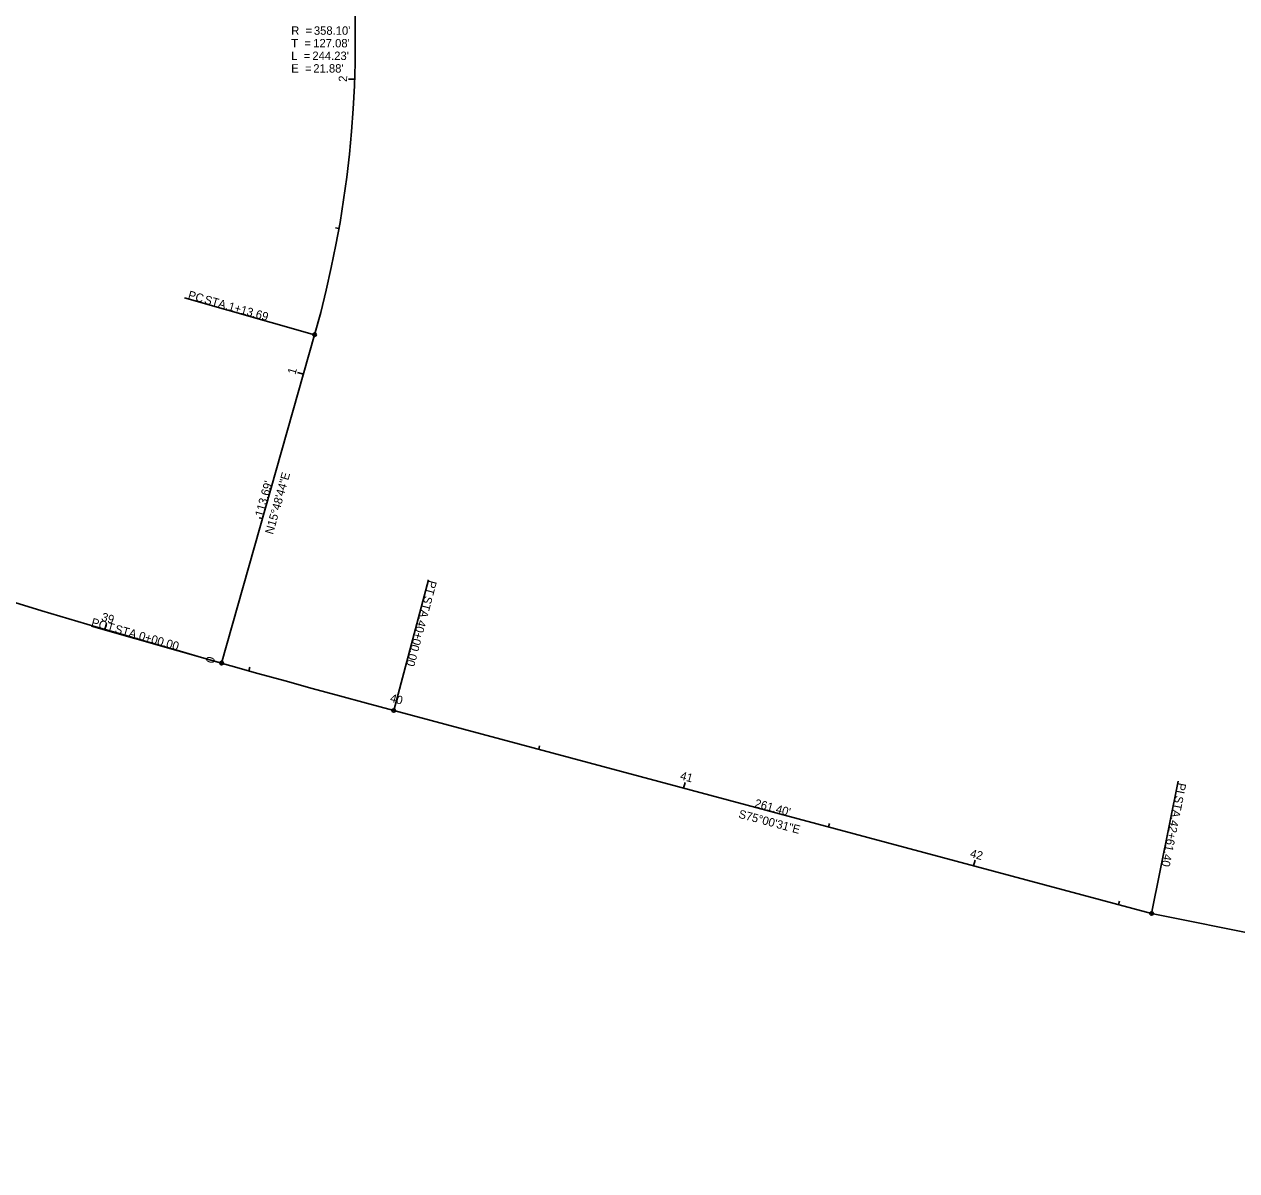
# Model space of a CAD drawing. Extents: x 1821160 to 1822741, y 497996 to 498758.
# Drawn here: x 1821926.9 to 1822330.8, y 497996.7 to 498378.6 of the extents above; entities that cross this region are included whole.
import ezdxf

# ---------------------------------------------------------------- set-up
doc = ezdxf.new("R2010")
doc.units = 0
for name, color, linetype in [('LT_X_Luminaires', 7, 'Continuous'), ('SC_Scratch1', 7, 'Continuous'), ('SC_Scratch20', 7, 'Continuous'), ('SV_P_Mon_Cells_Set', 7, 'Continuous'), ('SV_X_Control_Cells_Found', 7, 'Continuous'), ('SV_X_Mon_Cells_Found', 7, 'Continuous')]:
    doc.layers.add(name, color=color, linetype=linetype)

msp = doc.modelspace()

# ---------------------------------------------------------------- linework, layer by layer
at = {"layer": 'SC_Scratch1'}
for p, q in [((1822036.92, 498360.26), (1822034.92, 498360.33)), ((1822031.69, 498310.57), (1822030.51, 498310.78)), ((1822019.86, 498262.02), (1822017.93, 498262.57)), ((1822006.23, 498213.92), (1822005.08, 498214.24)), ((1821953.66, 498177.03), (1821954.22, 498178.95)), ((1821992.61, 498165.81), (1821990.68, 498166.35)), ((1822001.72, 498163.24), (1822002.04, 498164.4)), ((1822049.94, 498150.02), (1822050.46, 498151.95)), ((1822098.24, 498137.09), (1822098.55, 498138.25)), ((1822146.54, 498124.15), (1822147.05, 498126.08)), ((1822194.84, 498111.22), (1822195.15, 498112.38)), ((1822243.13, 498098.29), (1822243.65, 498100.22)), ((1822291.43, 498085.35), (1822291.74, 498086.51))]:
    msp.add_line(p, q, dxfattribs=at)
at = {"layer": 'SV_P_Mon_Cells_Set'}
for p, q in [((1821992.61, 498165.81), (1822023.59, 498275.19)), ((1822049.94, 498150.02), (1822302.44, 498082.4)), ((1822302.44, 498082.4), (1822729.2, 497996.72))]:
    msp.add_line(p, q, dxfattribs=at)
for centre, radius, start, end in [((1821679.04, 498372.77), 358.1, 344.1879, 23.264), ((1823136.37, 502207.06), 4199.99, 246.82358, 255.00869)]:
    msp.add_arc(centre, radius, start, end, dxfattribs=at)
at = {"layer": 'SV_X_Control_Cells_Found'}
for p, q in [((1822023.59, 498275.19), (1821980.29, 498287.46)), ((1822049.94, 498150.02), (1822061.58, 498193.49)), ((1821992.61, 498165.81), (1821949.31, 498178.07)), ((1822302.44, 498082.4), (1822311.3, 498126.52))]:
    msp.add_line(p, q, dxfattribs=at)
for centre in [(1822023.59, 498275.19), (1821992.61, 498165.81), (1822049.94, 498150.02), (1822302.44, 498082.4)]:
    msp.add_circle(centre, 0.6, dxfattribs=at)

# ---------------------------------------------------------------- texts
at = {"layer": 'LT_X_Luminaires'}
for s, p in [('R  = ', (1822015.8, 498375.1)), ("358.10'", (1822023.34, 498375.1)), ('T  = ', (1822015.8, 498370.9)), ("127.08'", (1822023.12, 498370.9)), ('L  = ', (1822015.8, 498366.7)), ("244.23'", (1822022.84, 498366.7)), ('E  = ', (1822015.8, 498362.5)), ("21.88'", (1822023.15, 498362.5))]:
    msp.add_text(s, height=2.8, dxfattribs=at).set_placement(p)
at = {"layer": 'SC_Scratch1'}
for s, rotation, p in [('2', 87.9979, (1822034.38, 498359.37)), ('1', 74.1879, (1822017.18, 498261.75)), ('39', 343.6445, (1821952.34, 498180.03)), ('0', 74.1879, (1821989.92, 498165.5)), ('40', 345.0087, (1822048.51, 498152.99)), ('41', 345.0087, (1822145.15, 498127.11)), ('42', 345.0087, (1822241.76, 498101.24))]:
    msp.add_text(s, height=2.8, rotation=rotation, dxfattribs=at).set_placement(p)
at = {"layer": 'SC_Scratch20'}
for s, rotation, p in [("113.69'", 74.1879, (1822006.31, 498214.32)), ("261.40'", 345.0087, (1822169.98, 498117.91))]:
    msp.add_text(s, height=2.8, rotation=rotation, dxfattribs=at).set_placement(p)
at = {"layer": 'SV_X_Control_Cells_Found'}
for s, rotation, p in [('PC', 344.1879, (1821981.2, 498287.24)), (' STA. ', 344.1879, (1821985.63, 498285.98)), ('1+13.69', 344.1879, (1821994.6, 498283.44)), ('PT', 255.0087, (1822061.64, 498193.57)), (' STA. ', 255.0087, (1822060.52, 498189.37)), ('POT', 344.1879, (1821948.97, 498178.21)), (' STA. ', 344.1879, (1821955.83, 498176.26)), ('40+00.00', 255.0087, (1822058.11, 498180.36)), ('0+00.00', 344.1879, (1821964.8, 498173.72)), ('PI', 258.6469, (1822311.25, 498126.1)), (' STA. ', 258.6469, (1822310.6, 498122.85)), ('42+61.40', 258.6469, (1822308.77, 498113.71))]:
    msp.add_text(s, height=2.8, rotation=rotation, dxfattribs=at).set_placement(p)
at = {"layer": 'SV_X_Mon_Cells_Found'}
for s, rotation, p in [('N15°48\'44"E', 74.1879, (1822009.69, 498208.5)), ('S75°00\'31"E', 345.0087, (1822164.61, 498114.34))]:
    msp.add_text(s, height=2.8, rotation=rotation, dxfattribs=at).set_placement(p)

doc.saveas('drawing.dxf')
